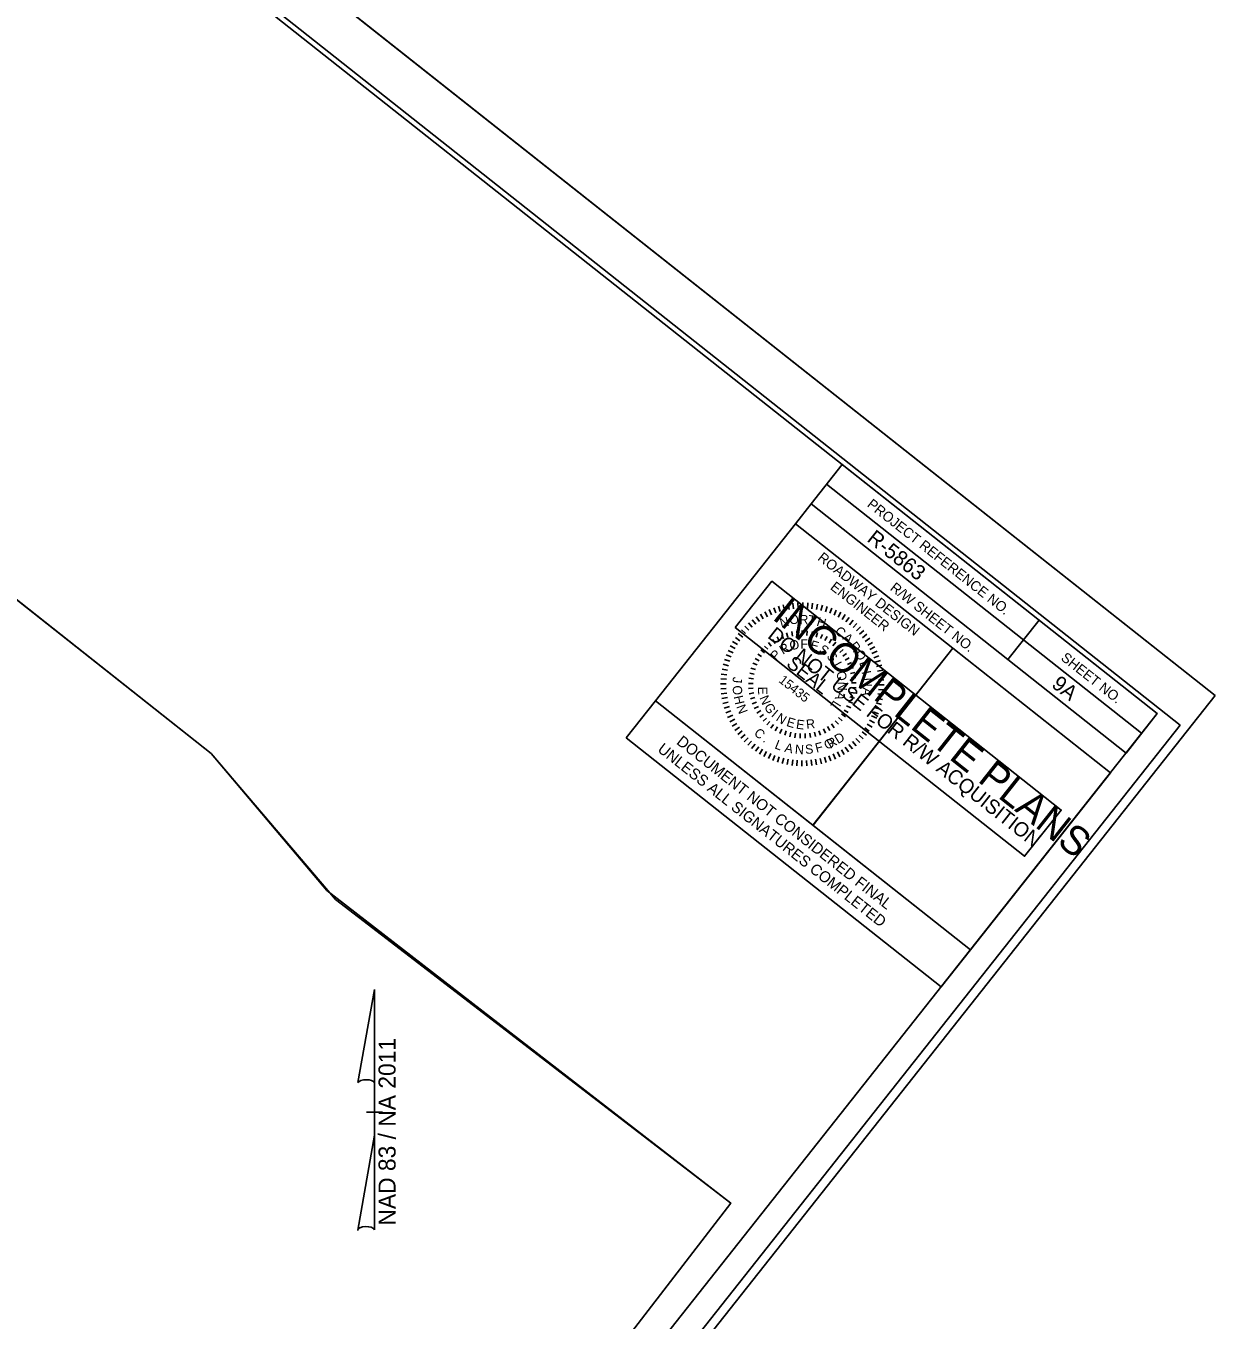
# Model space of a CAD drawing. Extents: x 556999 to 559002, y 505273 to 507273.
# Drawn here: x 558410 to 559002, y 505917 to 506562 of the extents above; entities that cross this region are included whole.
import ezdxf

# ---------------------------------------------------------------- set-up
doc = ezdxf.new("R2010")
doc.units = 0
for name, color, linetype in [('Matchline', 7, 'Continuous'), ('Old_Level_21', 7, 'Continuous'), ('Prop Horizontal Alignment Direction Label', 7, 'Continuous'), ('Prop Horizontal Alignment Station Label', 7, 'Continuous'), ('Prop SS Cut Line', 7, 'Continuous'), ('Prop SS Fill Line', 7, 'Continuous'), ('Prop SS Transition Line', 7, 'Continuous'), ('Scratch_Level_9', 7, 'Continuous'), ('Sheet Clip Boundary CELL', 7, 'Continuous'), ('Sheet Sticker Exception Certification CELL', 7, 'Continuous'), ('Sheet Sticker Incomplete CELL', 7, 'Continuous')]:
    doc.layers.add(name, color=color, linetype=linetype)

msp = doc.modelspace()

# ---------------------------------------------------------------- linework, layer by layer
at = {"layer": 'Matchline'}
for p, q in [((558069.07, 506542.35), (558502.21, 506199.86)), ((558502.21, 506199.86), (558559.93, 506131.49)), ((558559.93, 506131.49), (558761.1, 505975.77))]:
    msp.add_line(p, q, dxfattribs=at)
at = {"layer": 'Old_Level_21'}
for p, q in [((558778.08, 506270.43), (558779.35, 506267.97)), ((558780.29, 506271.5), (558781.42, 506268.96)), ((558782.57, 506272.43), (558783.54, 506269.83)), ((558784.9, 506273.22), (558785.71, 506270.56)), ((558787.27, 506273.86), (558787.92, 506271.16)), ((558789.68, 506274.36), (558790.17, 506271.63)), ((558792.12, 506274.72), (558792.43, 506271.96)), ((558794.57, 506274.93), (558794.72, 506272.16)), ((558797.03, 506274.99), (558797.01, 506272.21)), ((558799.48, 506274.9), (558799.3, 506272.13)), ((558801.93, 506274.66), (558801.58, 506271.91)), ((558804.36, 506274.28), (558803.85, 506271.55)), ((558806.76, 506273.74), (558806.08, 506271.06)), ((558809.13, 506273.07), (558808.29, 506270.43)), ((558811.45, 506272.26), (558810.45, 506269.67)), ((558813.72, 506271.3), (558812.56, 506268.78)), ((558815.92, 506270.21), (558814.62, 506267.77)), ((558769.96, 506264.91), (558771.79, 506262.82)), ((558771.86, 506266.47), (558773.56, 506264.28)), ((558773.85, 506267.92), (558775.42, 506265.62)), ((558775.92, 506269.24), (558777.35, 506266.85)), ((558818.06, 506268.99), (558816.61, 506266.63)), ((558820.11, 506267.64), (558818.52, 506265.37)), ((558822.09, 506266.17), (558820.36, 506264)), ((558823.97, 506264.59), (558822.12, 506262.52)), ((558763.41, 506257.6), (558765.69, 506256)), ((558764.88, 506259.57), (558767.06, 506257.85)), ((558766.47, 506261.45), (558768.54, 506259.6)), ((558768.17, 506263.23), (558770.12, 506261.26)), ((558784.17, 506257.96), (558785.26, 506255.91)), ((558786.52, 506259.06), (558787.4, 506256.92)), ((558788.95, 506259.94), (558789.63, 506257.72)), ((558791.47, 506260.57), (558791.93, 506258.31)), ((558794.03, 506260.96), (558794.27, 506258.66)), ((558796.62, 506261.11), (558796.63, 506258.79)), ((558799.21, 506261), (558799, 506258.69)), ((558801.78, 506260.64), (558801.35, 506258.37)), ((558804.3, 506260.04), (558803.65, 506257.81)), ((558806.75, 506259.19), (558805.89, 506257.04)), ((558809.11, 506258.11), (558808.05, 506256.06)), ((558825.75, 506262.89), (558823.78, 506260.94)), ((558827.42, 506261.09), (558825.34, 506259.26)), ((558828.99, 506259.2), (558826.8, 506257.49)), ((558830.44, 506257.2), (558828.14, 506255.64)), ((558759.76, 506251.2), (558762.28, 506250.04)), ((558760.84, 506253.41), (558763.29, 506252.1)), ((558762.07, 506255.54), (558764.43, 506254.09)), ((558776.17, 506251.45), (558777.94, 506249.97)), ((558777.92, 506253.36), (558779.55, 506251.72)), ((558779.85, 506255.09), (558781.31, 506253.3)), ((558781.94, 506256.62), (558783.22, 506254.7)), ((558811.35, 506256.81), (558810.1, 506254.87)), ((558813.46, 506255.3), (558812.03, 506253.49)), ((558812.03, 506253.49), (558813.46, 506255.3)), ((558815.41, 506253.59), (558813.81, 506251.93)), ((558817.19, 506251.7), (558815.43, 506250.2)), ((558831.76, 506255.13), (558829.37, 506253.71)), ((558832.95, 506252.98), (558830.49, 506251.7)), ((558834.02, 506250.76), (558831.48, 506249.64)), ((558757.31, 506244.25), (558760, 506243.56)), ((558757.98, 506246.61), (558760.63, 506245.77)), ((558758.8, 506248.93), (558761.39, 506247.93)), ((558772.11, 506244.83), (558774.24, 506243.92)), ((558773.25, 506247.16), (558775.28, 506246.06)), ((558774.61, 506249.38), (558776.52, 506248.08)), ((558818.78, 506249.65), (558816.88, 506248.33)), ((558820.16, 506247.46), (558818.15, 506246.32)), ((558821.32, 506245.14), (558819.21, 506244.2)), ((558834.95, 506248.48), (558832.34, 506247.52)), ((558835.73, 506246.15), (558833.08, 506245.35)), ((558756.39, 506239.41), (558759.15, 506239.07)), ((558756.78, 506241.85), (558759.51, 506241.33)), ((558770.55, 506239.9), (558772.81, 506239.42)), ((558771.21, 506242.4), (558773.42, 506241.7)), ((558822.26, 506242.72), (558820.06, 506241.99)), ((558822.96, 506240.22), (558820.7, 506239.71)), ((558836.38, 506243.78), (558833.68, 506243.13)), ((558836.88, 506241.37), (558834.15, 506240.89)), ((558837.24, 506238.94), (558834.48, 506238.62)), ((558756.07, 506234.51), (558758.84, 506234.49)), ((558756.13, 506232.05), (558758.9, 506232.2)), ((558756.16, 506236.97), (558758.93, 506236.78)), ((558769.95, 506234.75), (558772.27, 506234.71)), ((558770.03, 506232.16), (558772.34, 506232.34)), ((558770.13, 506237.34), (558772.42, 506237.07)), ((558823.41, 506237.67), (558821.11, 506237.38)), ((558823.57, 506232.49), (558821.26, 506232.64)), ((558823.61, 506235.09), (558821.3, 506235.01)), ((558837.42, 506231.57), (558834.65, 506231.76)), ((558837.45, 506236.49), (558834.67, 506236.34)), ((558837.5, 506234.03), (558834.73, 506234.05)), ((558756.34, 506229.6), (558759.09, 506229.92)), ((558756.69, 506227.17), (558759.43, 506227.65)), ((558757.2, 506224.76), (558759.89, 506225.41)), ((558770.36, 506229.59), (558772.64, 506229.99)), ((558770.94, 506227.06), (558773.16, 506227.68)), ((558771.75, 506224.6), (558773.91, 506225.43)), ((558821.94, 506224.91), (558819.77, 506225.72)), ((558822.73, 506227.38), (558820.49, 506227.97)), ((558823.27, 506229.92), (558820.99, 506230.29)), ((558836.26, 506224.29), (558833.57, 506224.98)), ((558836.8, 506226.69), (558834.07, 506227.21)), ((558837.18, 506229.13), (558834.43, 506229.47)), ((558757.84, 506222.39), (558760.5, 506223.19)), ((558758.63, 506220.06), (558761.23, 506221.02)), ((558759.56, 506217.78), (558762.1, 506218.9)), ((558772.81, 506222.23), (558774.87, 506223.27)), ((558774.08, 506219.97), (558776.04, 506221.2)), ((558777.38, 506219.27), (558775.55, 506217.85)), ((558818.21, 506218.11), (558816.37, 506219.5)), ((558819.67, 506220.25), (558817.7, 506221.46)), ((558820.92, 506222.53), (558818.84, 506223.54)), ((558833.82, 506217.34), (558831.3, 506218.5)), ((558834.78, 506219.61), (558832.18, 506220.61)), ((558835.59, 506221.93), (558832.94, 506222.77)), ((558760.63, 506215.56), (558763.09, 506216.84)), ((558761.82, 506213.41), (558764.2, 506214.83)), ((558763.14, 506211.34), (558765.43, 506212.9)), ((558777.25, 506215.87), (558778.93, 506217.46)), ((558779.12, 506214.07), (558780.64, 506215.81)), ((558781.15, 506212.46), (558782.5, 506214.34)), ((558783.33, 506211.05), (558784.49, 506213.05)), ((558785.63, 506209.86), (558786.59, 506211.97)), ((558808.25, 506210.01), (558807.26, 506212.1)), ((558810.53, 506211.22), (558809.35, 506213.21)), ((558812.7, 506212.65), (558811.33, 506214.52)), ((558813.22, 506216.07), (558814.77, 506214.35)), ((558816.55, 506216.12), (558814.85, 506217.68)), ((558830.16, 506210.94), (558827.89, 506212.53)), ((558831.51, 506213), (558829.14, 506214.45)), ((558832.73, 506215.13), (558830.28, 506216.44)), ((558764.59, 506209.34), (558766.78, 506211.05)), ((558766.15, 506207.45), (558768.24, 506209.28)), ((558767.83, 506205.65), (558769.8, 506207.6)), ((558769.61, 506203.95), (558771.46, 506206.02)), ((558788.04, 506208.9), (558788.79, 506211.09)), ((558790.53, 506208.18), (558791.07, 506210.43)), ((558793.08, 506207.69), (558793.4, 506209.98)), ((558795.66, 506207.46), (558795.76, 506209.77)), ((558798.25, 506207.47), (558798.12, 506209.78)), ((558800.83, 506207.74), (558800.48, 506210.02)), ((558803.37, 506208.25), (558802.8, 506210.49)), ((558805.85, 506209.01), (558805.07, 506211.19)), ((558823.61, 506203.63), (558821.78, 506205.72)), ((558825.41, 506205.31), (558823.46, 506207.28)), ((558827.11, 506207.09), (558825.04, 506208.94)), ((558828.69, 506208.97), (558826.52, 506210.69)), ((558771.49, 506202.37), (558773.21, 506204.54)), ((558773.46, 506200.9), (558775.05, 506203.17)), ((558775.52, 506199.55), (558776.97, 506201.91)), ((558777.65, 506198.33), (558778.96, 506200.77)), ((558779.86, 506197.24), (558781.01, 506199.76)), ((558813.28, 506197.04), (558812.16, 506199.58)), ((558815.5, 506198.11), (558814.22, 506200.57)), ((558817.65, 506199.3), (558816.23, 506201.69)), ((558819.72, 506200.62), (558818.15, 506202.92)), ((558821.71, 506202.07), (558820.01, 506204.26)), ((558782.13, 506196.28), (558783.13, 506198.87)), ((558784.44, 506195.47), (558785.28, 506198.11)), ((558786.81, 506194.8), (558787.49, 506197.48)), ((558789.21, 506194.26), (558789.73, 506196.99)), ((558791.64, 506193.88), (558791.99, 506196.63)), ((558794.09, 506193.64), (558794.27, 506196.41)), ((558796.55, 506193.55), (558796.56, 506196.33)), ((558799.01, 506193.61), (558798.86, 506196.38)), ((558801.46, 506193.82), (558801.14, 506196.58)), ((558803.89, 506194.18), (558803.41, 506196.91)), ((558806.3, 506194.68), (558805.65, 506197.38)), ((558808.67, 506195.32), (558807.86, 506197.98)), ((558811, 506196.11), (558810.04, 506198.71))]:
    msp.add_line(p, q, dxfattribs=at)
at = {"layer": 'Prop Horizontal Alignment Direction Label'}
msp.add_lwpolyline([(559002.42, 506228.78), (557681.46, 507273.25), (556999.2, 506410.4), (558320.16, 505365.92)], close=True, dxfattribs=at)
at = {"layer": 'Prop Horizontal Alignment Station Label'}
for p, q in [((558575.39, 506035.83), (558583.59, 506082.18)), ((558583.64, 506082.18), (558583.59, 506082.18)), ((558583.64, 506082.18), (558583.59, 506082.18)), ((558583.64, 506082.18), (558583.64, 506034.38)), ((558583.64, 506009.58), (558583.64, 506035.78)), ((558583.64, 506034.38), (558583.64, 506035.73)), ((558579.64, 506021.18), (558579.59, 506021.18)), ((558583.19, 506021.18), (558579.64, 506021.18)), ((558579.69, 506021.18), (558587.69, 506021.18)), ((558583.64, 506009.58), (558575.29, 505962.33)), ((558583.69, 505962.53), (558583.64, 506009.58))]:
    msp.add_line(p, q, dxfattribs=at)
for centre, start_param, end_param in [((558579.52, 506035.34), 0.216388, 2.908219), ((558579.52, 505962.17), 0.201328, 3.141593)]:
    msp.add_ellipse(centre, major_axis=(4.23, -0.03), ratio=0.461098, start_param=start_param, end_param=end_param, dxfattribs=at)
at = {"layer": 'Prop SS Cut Line'}
for p, q in [((558808.87, 506333.95), (558965.79, 506209.87)), ((558801.12, 506324.14), (558793.36, 506314.33)), ((558801.12, 506324.14), (558958.04, 506200.06)), ((558801.12, 506324.14), (558958.04, 506200.06)), ((558914.71, 506266.19), (558899.21, 506246.58)), ((558871.84, 506252.28), (558802.1, 506164.07))]:
    msp.add_line(p, q, dxfattribs=at)
for points in [[(558973.57, 506219.71), (557796.95, 507150.06), (557145.7, 506326.43), (558322.33, 505396.07)], [(558816.65, 506343.79), (558973.57, 506219.71), (558958.04, 506200.06), (558801.12, 506324.14)], [(558793.36, 506314.33), (558871.84, 506252.28), (558802.07, 506164.03), (558723.59, 506226.09)], [(558871.84, 506252.28), (558950.28, 506190.26), (558880.51, 506102.01), (558802.07, 506164.03)]]:
    msp.add_lwpolyline(points, close=True, dxfattribs=at)
at = {"layer": 'Prop SS Fill Line'}
msp.add_lwpolyline([(558984.96, 506213.96), (557677.73, 507247.58), (557023.32, 506419.94), (558330.55, 505386.32)], close=True, dxfattribs=at)
at = {"layer": 'Scratch_Level_9'}
msp.add_line((559002.42, 506228.78), (557681.46, 507273.25), dxfattribs=at)
at = {"layer": 'Sheet Clip Boundary CELL'}
msp.add_lwpolyline([(558069.07, 506542.35), (558502.21, 506199.86), (558564.29, 506127.01), (558761.1, 505975.77), (558323.19, 505407.07), (558300.81, 505488.36), (558208.66, 505547.92), (558125.54, 505588.21), (558099.51, 505637.12), (558051.88, 505660.91), (558034.88, 505701.52), (557812.51, 505806.82), (557719.93, 505881.17), (557819.13, 505983.86), (557736.69, 506155.68), (557811.36, 506249.18), (557937.11, 506307.83), (558003.47, 506383.71), (558026.52, 506432.18), (558000.13, 506451.2)], close=True, dxfattribs=at)
at = {"layer": 'Sheet Sticker Exception Certification CELL'}
for p, q in [((558709.01, 506207.65), (558723.59, 506226.09)), ((558723.59, 506226.09), (558880.5, 506102.02)), ((558865.92, 506083.58), (558709.01, 506207.65)), ((558880.49, 506102.01), (558865.92, 506083.57))]:
    msp.add_line(p, q, dxfattribs=at)
at = {"layer": 'Sheet Sticker Incomplete CELL'}
msp.add_lwpolyline([(558763.37, 506262.57), (558781.59, 506285.61), (558925.73, 506171.64), (558907.51, 506148.6)], close=True, dxfattribs=at)

# ---------------------------------------------------------------- texts
at = {"layer": 'Old_Level_21'}
for s, height, rotation, p in [('N', 4.62, 15.26356, (558786.28, 506262.43)), ('O', 4.62, 13.30413, (558790.79, 506263.84)), ('R', 4.62, 0.24739, (558795.34, 506264.2)), ('T', 4.62, 352.08643, (558799.39, 506264.29)), ('H', 4.62, 342.65448, (558803.55, 506263.56)), ('C', 4.62, 318.94379, (558812.6, 506260.17)), ('A', 4.62, 318.94379, (558816.51, 506256.96)), ('P', 4.62, 45.71618, (558783.68, 506245.83)), ('R', 4.62, 30.41993, (558787.07, 506248.98)), ('O', 4.62, 15.12369, (558791.08, 506251.1)), ('F', 4.62, 359.82744, (558795.81, 506252.11)), ('E', 4.62, 344.5312, (558800.33, 506251.86)), ('S', 4.62, 329.23495, (558804.72, 506250.41)), ('R', 4.62, 306.93449, (558819.92, 506253.38)), ('O', 4.62, 303.87767, (558822.6, 506249.56)), ('SEAL', 6.938, 321.58683, (558788.34, 506243.63)), ('S', 4.62, 313.93871, (558808.58, 506247.84)), ('I', 4.62, 298.64246, (558811.81, 506244.01)), ('L', 4.62, 290.74139, (558825.01, 506245.02)), ('J', 4.62, 265.52184, (558762.24, 506238.11)), ('15435', 4.622, 321.58683, (558784.68, 506235.67)), ('O', 4.62, 283.34621, (558813.61, 506240.28)), ('I', 4.62, 281.16592, (558826.26, 506240.6)), ('O', 4.62, 273.59366, (558762.02, 506233.59)), ('E', 4.62, 271.65692, (558774.69, 506233.06)), ('N', 4.62, 268.04997, (558814.47, 506235.64)), ('A', 4.62, 262.10393, (558826.99, 506232.89)), ('N', 4.62, 271.87146, (558826.72, 506237.46)), ('H', 4.62, 282.23641, (558762.55, 506228.19)), ('N', 4.62, 292.51199, (558775.33, 506227.63)), ('L', 4.62, 237.45748, (558812.44, 506226.59)), ('A', 4.62, 252.75372, (558814.11, 506231.1)), ('N', 4.62, 290.90899, (558763.82, 506223.2)), ('G', 4.62, 301.27823, (558777.53, 506223.12)), ('I', 4.62, 319.37302, (558780.93, 506218.54)), ('N', 4.62, 327.00268, (558783.29, 506216.47)), ('C', 4.62, 317.67678, (558772.34, 506209.54)), ('E', 4.62, 342.39475, (558788.52, 506213.64)), ('E', 4.62, 352.38063, (558793.46, 506212.24)), ('R', 4.62, 6.15172, (558798.91, 506212.03)), ('.', 4.62, 325.41913, (558776.77, 506205.88)), ('L', 4.62, 338.20345, (558782.67, 506202.5)), ('F', 4.62, 13.79388, (558803.8, 506200.22)), ('O ', 4.622, 22.5865, (558808.75, 506201.62)), (' RD', 4.622, 31.25925, (558809.29, 506201.22)), ('A', 4.62, 347.20601, (558787.64, 506200.72)), ('N', 4.62, 356.02863, (558792.96, 506199.71)), ('S', 4.62, 4.91126, (558798.35, 506199.54))]:
    msp.add_text(s, height=height, rotation=rotation, dxfattribs=at).set_placement(p)
at = {"layer": 'Prop Horizontal Alignment Station Label'}
msp.add_text('NAD 83 / NA 2011', height=8.5, rotation=90, dxfattribs=at).set_placement((558594.16, 505964.59))
at = {"layer": 'Prop SS Cut Line'}
for s, height, p in [('PROJECT REFERENCE NO.', 5.0001, (558828.67, 506323.2)), ('ROADWAY DESIGN', 5.0001, (558804.05, 506296.58)), ('ENGINEER', 5, (558810.31, 506282)), ('R/W SHEET NO.', 5.0001, (558840.12, 506281.57)), ('SHEET NO.', 5, (558925.21, 506246.74))]:
    msp.add_text(s, height=height, rotation=321.66667, dxfattribs=at).set_placement(p)
at = {"layer": 'Prop SS Transition Line'}
for s, p in [('R-5863   ', (558828.57, 506305.94)), ('9A  ', (558920.49, 506233.32))]:
    msp.add_text(s, height=7.5, rotation=321.66667, dxfattribs=at).set_placement(p)
at = {"layer": 'Sheet Sticker Exception Certification CELL'}
for s, p in [('DOCUMENT NOT CONSIDERED FINAL', (558733.7, 506204.9)), ('UNLESS ALL SIGNATURES COMPLETED', (558724.26, 506201.15))]:
    msp.add_text(s, height=5.5, rotation=321.66667, dxfattribs=at).set_placement(p)
at = {"layer": 'Sheet Sticker Incomplete CELL'}
for s, height, p in [('INCOMPLETE PLANS', 14.4, (558781.24, 506267.11)), ('DO NOT USE FOR R/W ACQUISITION', 7.2, (558779.04, 506257.77))]:
    msp.add_text(s, height=height, rotation=321.66667, dxfattribs=at).set_placement(p)

doc.saveas('drawing.dxf')
